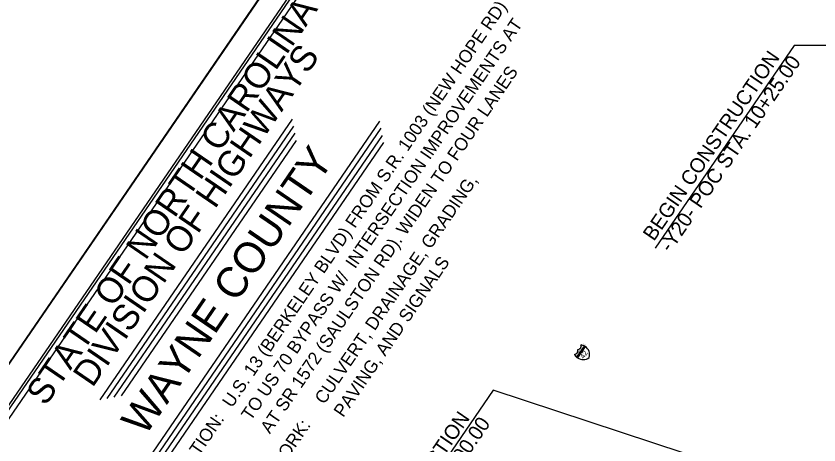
# Model space of a CAD drawing. Extents: x 2312641 to 2338852, y 590461 to 618614.
# Drawn here: x 2318683 to 2329669, y 606464 to 612333 of the extents above; entities that cross this region are included whole.
import ezdxf

# ---------------------------------------------------------------- set-up
doc = ezdxf.new("R2010")
doc.units = 0
for name, color, linetype in [('Default', 7, 'Continuous'), ('Exist Other Culture Sign Post Text', 7, 'Continuous'), ('Exist Property Iron Pin Cogo Number', 7, 'Continuous'), ('Exist Roads Curbs Text', 7, 'Continuous'), ('Exist Structure Minor Pipes RCP 15 Inch Text', 7, 'Continuous'), ('Exist Utilities Power Joint Use Telephone CELL', 7, 'Continuous'), ('Exist Utilities Power Joint Use Telephone Text', 7, 'Continuous'), ('Exist Vegetation Woods Line Text', 7, 'Continuous')]:
    doc.layers.add(name, color=color, linetype=linetype)

msp = doc.modelspace()

# ---------------------------------------------------------------- linework, layer by layer
at = {"layer": 'Default'}
for p, q in [((2326358, 607663), (2326463, 607816)), ((2326463, 607816), (2326358, 607662)), ((2326358, 607663), (2326463, 607816)), ((2326366, 607656), (2326472, 607810)), ((2326472, 607810), (2326366, 607656)), ((2326366, 607656), (2326472, 607810)), ((2326358, 607662), (2326358, 607663))]:
    msp.add_line(p, q, dxfattribs=at)
for centre, radius, start, end in [((2326317, 607755), 52.4, 277.8759, 14.4267), ((2326362, 607820), 52.4, 276.7255, 13.2763), ((2326398, 607700), 133, 60.3904, 83.4009), ((2326398, 607700), 133, 56.1286, 60.3887), ((2326398, 607700), 133, 342.779, 56.1166), ((2326442, 607765), 133, 207.7515, 230.7405), ((2326442, 607765), 133, 230.7617, 235.0231), ((2326442, 607765), 133, 235.0416, 308.3732)]:
    msp.add_arc(centre, radius, start, end, dxfattribs=at)
at = {"layer": 'Exist Other Culture Sign Post Text'}
msp.add_line((2312821, 599167), (2326149, 618614), dxfattribs=at)
at = {"layer": 'Exist Property Iron Pin Cogo Number'}
for p, q in [((2319833, 607081), (2322466, 610924)), ((2319930, 607099), (2322485, 610826)), ((2320290, 605976), (2323662, 610895)), ((2320027, 607117), (2322503, 610729)), ((2320388, 605994), (2323680, 610798)), ((2320125, 607135), (2322521, 610632)), ((2320485, 606012), (2323698, 610700)), ((2320582, 606030), (2323717, 610603))]:
    msp.add_line(p, q, dxfattribs=at)
for points in [[(2326224, 618105), (2314511, 601013)], [(2326242, 618007), (2315004, 601609)]]:
    msp.add_lwpolyline(points, dxfattribs=at)
at = {"layer": 'Exist Roads Curbs Text'}
msp.add_line((2323394, 609527), (2323394, 609527), dxfattribs=at)
at = {"layer": 'Exist Structure Minor Pipes RCP 15 Inch Text'}
for p, q in [((2329329, 611931), (2327427, 609155)), ((2331448, 611928), (2329329, 611931)), ((2325213, 607214), (2323318, 604449)), ((2328430, 606154), (2325213, 607214))]:
    msp.add_line(p, q, dxfattribs=at)
at = {"layer": 'Exist Utilities Power Joint Use Telephone CELL'}
msp.add_lwpolyline([(2326149, 618614), (2312821, 599167), (2325524, 590461), (2338852, 609909)], close=True, dxfattribs=at)
at = {"layer": 'Exist Utilities Power Joint Use Telephone Text'}
msp.add_lwpolyline([(2325368, 590789), (2338557, 610034), (2326373, 618385), (2313184, 599139)], close=True, dxfattribs=at)

# ---------------------------------------------------------------- texts
at = {"layer": 'Default'}
for s, height, p in [('INTERSTATE', 23.4, (2326359, 607671)), ('42', 70.3, (2326450, 607636))]:
    msp.add_text(s, height=height, rotation=55.5761, dxfattribs=at).set_placement(p)
at = {"layer": 'Exist Property Iron Pin Cogo Number'}
for s, height, p in [('STATE OF NORTH CAROLINA', 350, (2319088, 606984)), ('DIVISION OF HIGHWAYS', 350, (2319729, 607238)), ('LOCATION: ', 175, (2320827, 605781)), ('TYPE OF WORK:', 175, (2321671, 605203))]:
    msp.add_text(s, height=height, rotation=55.5761, dxfattribs=at).set_placement(p)
at = {"layer": 'Exist Structure Minor Pipes RCP 15 Inch Text'}
for s, p in [('BEGIN CONSTRUCTION', (2327411, 609242)), ('-Y20- POC STA. 10+25.00', (2327636, 609087)), ('END CONSTRUCTION', (2323322, 604528)), ('-L- POT STA 125+00.00', (2323547, 604373))]:
    msp.add_text(s, height=200, rotation=55.5761, dxfattribs=at).set_placement(p)
at = {"layer": 'Exist Vegetation Woods Line Text'}
for s, height, p in [('U.S. 13 (BERKELEY BLVD) FROM S.R. 1003 (NEW HOPE RD)', 175, (2321636, 606962)), ('TO US 70 BYPASS W/  INTERSECTION IMPROVEMENTS AT', 175, (2321896, 606784)), ('AT SR 1572 (SAULSTON RD). WIDEN TO FOUR LANES', 175, (2322156, 606606)), ('WAYNE COUNTY', 420, (2320446, 606571)), ('CULVERT, DRAINAGE, GRADING,', 175, (2322900, 607009)), ('PAVING, AND SIGNALS', 175, (2323160, 606831))]:
    msp.add_text(s, height=height, rotation=55.5761, dxfattribs=at).set_placement(p)

doc.saveas('drawing.dxf')
